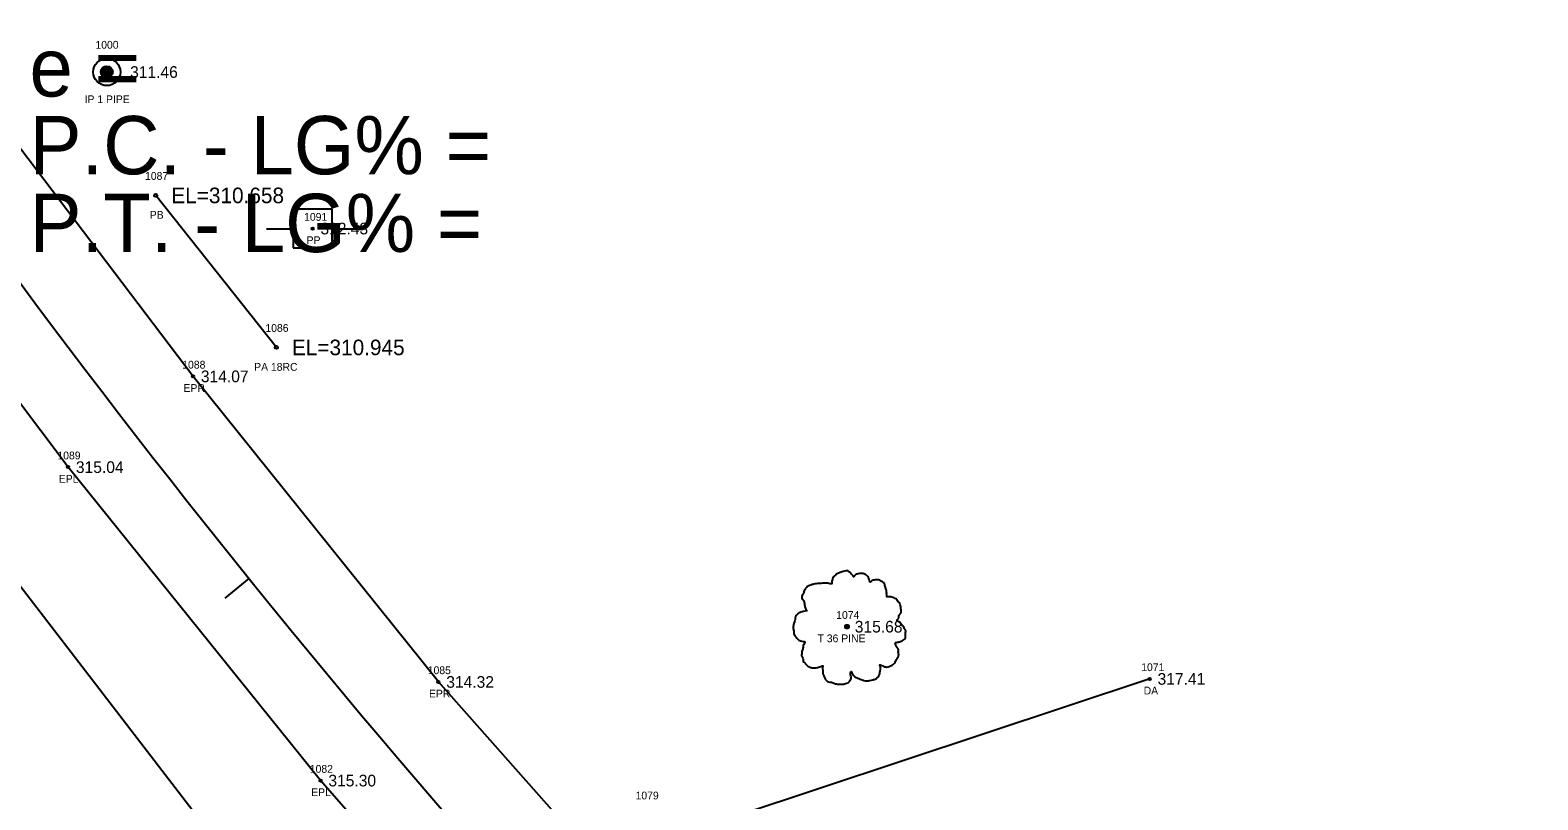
# Model space of a CAD drawing. Extents: x 1865045 to 1867370, y 910391 to 914218.
# Drawn here: x 1866620.1 to 1866814, y 910574.6 to 910673.5 of the extents above; entities that cross this region are included whole.
import ezdxf

# ---------------------------------------------------------------- set-up
doc = ezdxf.new("R2010")
doc.units = 0
for name, color, linetype in [('RD_EX_DR_Pipe', 7, 'Continuous'), ('RD_EX_DR_Pipe_txCode', 7, 'Continuous'), ('RD_EX_Driveway', 7, 'Continuous'), ('RD_EX_Driveway_txCode', 7, 'Continuous'), ('RD_EX_DV_Prop_txCode', 7, 'Continuous'), ('RD_EX_DV_PropPin', 7, 'Continuous'), ('RD_EX_Road', 7, 'Continuous'), ('RD_EX_Road_txCode', 7, 'Continuous'), ('RD_EX_TX_Driveway_ELEV', 7, 'Continuous'), ('RD_EX_TX_DV_Prop_ELEV', 7, 'Continuous'), ('RD_EX_TX_Road_ELEV', 7, 'Continuous'), ('RD_EX_TX_VEG_ELEV', 7, 'Continuous'), ('RD_EX_UT', 7, 'Continuous'), ('RD_EX_UT_txCode', 7, 'Continuous'), ('RD_EX_VEG', 7, 'Continuous'), ('RD_EX_VEG_txCode', 7, 'Continuous'), ('RD_HC_Cl', 7, 'Continuous'), ('RD_HC_Data', 7, 'Continuous'), ('RD_HC_Data_Tic', 7, 'Continuous'), ('RD_HC_Survey_ELEV', 7, 'Continuous'), ('RD_SMD_Locator', 7, 'Continuous'), ('RD_TX_Pipe_ElevEX', 7, 'Continuous')]:
    doc.layers.add(name, color=color, linetype=linetype)

msp = doc.modelspace()

# ---------------------------------------------------------------- linework, layer by layer
at = {"layer": 'RD_EX_DR_Pipe'}
msp.add_line((1866651.75, 910632.75), (1866636.24, 910652.29), dxfattribs=at)
at = {"layer": 'RD_EX_Driveway'}
msp.add_line((1866764.08, 910590.14), (1866711.01, 910572.54), dxfattribs=at)
at = {"layer": 'RD_EX_DV_PropPin'}
for p, q in [((1866629.21, 910667.96), (1866629.21, 910668.35)), ((1866629.24, 910667.85), (1866629.24, 910668.45)), ((1866629.28, 910667.78), (1866629.28, 910668.52)), ((1866629.31, 910667.73), (1866629.31, 910668.58)), ((1866629.35, 910667.68), (1866629.35, 910668.63)), ((1866629.38, 910667.64), (1866629.38, 910668.67)), ((1866629.42, 910667.6), (1866629.42, 910668.7)), ((1866629.45, 910667.57), (1866629.45, 910668.73)), ((1866629.49, 910667.54), (1866629.49, 910668.76)), ((1866629.52, 910667.52), (1866629.52, 910668.79)), ((1866629.56, 910667.5), (1866629.56, 910668.81)), ((1866629.59, 910667.48), (1866629.59, 910668.83)), ((1866629.63, 910667.46), (1866629.63, 910668.85)), ((1866629.66, 910667.45), (1866629.66, 910668.86)), ((1866629.7, 910667.43), (1866629.7, 910668.87)), ((1866629.73, 910667.42), (1866629.73, 910668.88)), ((1866629.77, 910667.41), (1866629.77, 910668.89)), ((1866629.8, 910667.4), (1866629.8, 910668.9)), ((1866629.84, 910667.4), (1866629.84, 910668.91)), ((1866629.87, 910667.4), (1866629.87, 910668.91)), ((1866629.91, 910667.39), (1866629.91, 910668.91)), ((1866629.94, 910667.39), (1866629.94, 910668.91)), ((1866629.98, 910667.39), (1866629.98, 910668.91)), ((1866630.01, 910667.4), (1866630.01, 910668.91)), ((1866630.05, 910667.4), (1866630.05, 910668.91)), ((1866630.08, 910667.4), (1866630.08, 910668.9)), ((1866630.12, 910667.41), (1866630.12, 910668.89)), ((1866630.15, 910667.42), (1866630.15, 910668.88)), ((1866630.19, 910667.43), (1866630.19, 910668.87)), ((1866630.22, 910667.45), (1866630.22, 910668.86)), ((1866630.26, 910667.46), (1866630.26, 910668.85)), ((1866630.29, 910667.48), (1866630.29, 910668.83)), ((1866630.33, 910667.5), (1866630.33, 910668.81)), ((1866630.36, 910667.52), (1866630.36, 910668.79)), ((1866630.4, 910667.54), (1866630.4, 910668.76)), ((1866630.43, 910667.57), (1866630.43, 910668.73)), ((1866630.47, 910667.6), (1866630.47, 910668.7)), ((1866630.51, 910667.64), (1866630.51, 910668.67)), ((1866630.54, 910667.68), (1866630.54, 910668.63)), ((1866630.58, 910667.73), (1866630.58, 910668.58)), ((1866630.61, 910667.78), (1866630.61, 910668.52)), ((1866630.65, 910667.85), (1866630.65, 910668.45)), ((1866630.68, 910667.96), (1866630.68, 910668.35))]:
    msp.add_line(p, q, dxfattribs=at)
for radius in [1.75, 0.761]:
    msp.add_circle((1866629.94, 910668.15), radius, dxfattribs=at)
at = {"layer": 'RD_EX_Road'}
for points in [[(1866813.99, 910446.88), (1866778.44, 910479.3), (1866742.34, 910514.45), (1866706.87, 910550.71), (1866695.16, 910564.33), (1866672.6, 910589.75), (1866641.04, 910629.03), (1866609.7, 910670.28), (1866582.23, 910711.25), (1866556.44, 910754.58), (1866532.04, 910798.87), (1866507.56, 910846.03), (1866483.5, 910895.43), (1866461.16, 910941.96), (1866414.86, 911037.95), (1866406.11, 911034.1)], [(1866800.58, 910432.45), (1866764.32, 910465.74), (1866727.39, 910500.95), (1866691.9, 910537.68), (1866657.44, 910577.07), (1866624.97, 910617.36), (1866593.69, 910658.89), (1866565.16, 910701.48), (1866538.98, 910745.57), (1866531.34, 910758.5), (1866513.94, 910791.05), (1866489.48, 910838.44), (1866465.73, 910886.02), (1866443.47, 910933.62), (1866397.5, 911029.82), (1866406.11, 911034.1)]]:
    msp.add_lwpolyline(points, dxfattribs=at)
at = {"layer": 'RD_EX_UT'}
for p, q in [((1866658.91, 910650.54), (1866653.91, 910650.54)), ((1866653.91, 910650.54), (1866653.91, 910645.54)), ((1866658.91, 910645.54), (1866658.91, 910650.54)), ((1866650.48, 910647.98), (1866653.95, 910647.98)), ((1866658.84, 910647.98), (1866662.48, 910647.98)), ((1866653.91, 910645.54), (1866658.91, 910645.54))]:
    msp.add_line(p, q, dxfattribs=at)
at = {"layer": 'RD_EX_VEG'}
msp.add_lwpolyline([(1866770.74, 910392.93), (1866734.38, 910438.07), (1866709.99, 910485.53), (1866679.02, 910526.15), (1866645.41, 910567.43), (1866612.91, 910609.64), (1866580.57, 910649.92), (1866452.86, 910898.44)], dxfattribs=at)
for centre, radius in [((1866725.14, 910596.85), 0.25), ((1866725.12, 910596.83), 0.0001)]:
    msp.add_circle(centre, radius, dxfattribs=at)
for points in [[(1866725.27, 910604.01), (1866724.97, 910604.04), (1866724.64, 910603.94), (1866724.39, 910603.84), (1866724.17, 910603.77), (1866723.94, 910603.67), (1866723.64, 910603.49), (1866723.42, 910603.29), (1866723.29, 910603.04), (1866723.24, 910602.82), (1866723.19, 910602.54), (1866723.19, 910602.37), (1866723.07, 910602.34), (1866722.92, 910602.37), (1866722.67, 910602.44), (1866722.42, 910602.44), (1866722.17, 910602.44), (1866721.82, 910602.42), (1866721.47, 910602.42), (1866721.19, 910602.37), (1866720.87, 910602.32), (1866720.49, 910602.19), (1866720.14, 910602.07), (1866719.85, 910601.82), (1866719.6, 910601.34), (1866719.47, 910600.99), (1866719.32, 910600.74), (1866719.47, 910600.29), (1866719.65, 910599.94), (1866719.67, 910599.74), (1866719.75, 910599.32), (1866719.85, 910599.09), (1866719.97, 910598.89), (1866719.9, 910598.87), (1866719.52, 910598.82), (1866719.22, 910598.72), (1866718.8, 910598.49), (1866718.57, 910598.27), (1866718.47, 910597.94), (1866718.45, 910597.59), (1866718.35, 910597.39), (1866718.27, 910597.12), (1866718.25, 910597.04), (1866718.2, 910596.72), (1866718.3, 910596.27), (1866718.32, 910595.92), (1866718.45, 910595.69), (1866718.6, 910595.52), (1866718.77, 910595.27), (1866719.17, 910595.04), (1866719.5, 910594.94), (1866719.7, 910594.92), (1866719.52, 910594.42), (1866719.47, 910594.07), (1866719.35, 910593.67), (1866719.35, 910593.59), (1866719.3, 910593.12), (1866719.45, 910592.79), (1866719.52, 910592.42), (1866719.7, 910592.2), (1866719.97, 910591.9), (1866720.29, 910591.67), (1866720.79, 910591.55), (1866721.19, 910591.57), (1866721.77, 910591.75), (1866722.02, 910591.82), (1866721.99, 910591.65), (1866722.02, 910591.27), (1866722.02, 910590.85), (1866722.17, 910590.52), (1866722.27, 910590.25), (1866722.42, 910590), (1866722.74, 910589.77), (1866723.14, 910589.7), (1866723.57, 910589.55), (1866724.02, 910589.47), (1866724.52, 910589.45), (1866725.12, 910589.6), (1866725.39, 910589.72), (1866725.49, 910589.9), (1866725.69, 910590.27), (1866725.64, 910590.5), (1866725.67, 910591.1), (1866725.77, 910590.92), (1866725.94, 910590.57), (1866726.44, 910590.27), (1866726.84, 910590.1), (1866727.32, 910589.95), (1866727.62, 910589.87), (1866728.09, 910589.95), (1866728.47, 910590.02), (1866728.84, 910590.15), (1866729.14, 910590.42), (1866729.32, 910590.7), (1866729.37, 910590.97), (1866729.44, 910591.35), (1866729.49, 910591.52)], [(1866729.49, 910591.52), (1866729.42, 910591.7), (1866729.37, 910591.95), (1866729.44, 910591.92), (1866729.62, 910591.87), (1866729.89, 910591.75), (1866730.12, 910591.67), (1866730.44, 910591.7), (1866730.72, 910591.8), (1866731.17, 910592.07), (1866731.44, 910592.54), (1866731.71, 910592.94), (1866731.79, 910593.27), (1866731.74, 910593.49), (1866731.71, 910593.99), (1866731.51, 910594.24), (1866731.46, 910594.37), (1866731.36, 910594.77), (1866731.44, 910594.82), (1866731.71, 910594.87), (1866732.09, 910594.99), (1866732.36, 910595.12), (1866732.59, 910595.29), (1866732.66, 910595.52), (1866732.64, 910595.92), (1866732.69, 910596.32), (1866732.61, 910596.47), (1866732.51, 910596.62), (1866732.44, 910596.82), (1866732.29, 910596.97), (1866732.19, 910597.12), (1866732.09, 910597.22), (1866731.96, 910597.37), (1866731.79, 910597.49), (1866731.64, 910597.54), (1866731.59, 910597.69), (1866731.74, 910597.89), (1866731.79, 910597.99), (1866731.81, 910598.22), (1866732.04, 910598.57), (1866732.09, 910598.97), (1866732.04, 910599.39), (1866731.99, 910599.67), (1866731.84, 910599.94), (1866731.64, 910600.19), (1866731.51, 910600.37), (1866731.34, 910600.49), (1866731.02, 910600.62), (1866730.77, 910600.67), (1866730.42, 910600.67), (1866730.22, 910600.72), (1866730.24, 910600.77), (1866730.24, 910600.92), (1866730.24, 910601.19), (1866730.17, 910601.64), (1866730.02, 910602.14), (1866730.02, 910602.17), (1866729.92, 910602.42), (1866729.69, 910602.62), (1866729.52, 910602.72), (1866729.32, 910602.84), (1866729.07, 910602.87), (1866728.77, 910602.87), (1866728.49, 910602.82), (1866728.29, 910602.72), (1866728.12, 910602.59), (1866728.04, 910602.74), (1866727.94, 910603.04), (1866727.89, 910603.19), (1866727.74, 910603.37), (1866727.52, 910603.57), (1866727.07, 910603.69), (1866726.44, 910603.62), (1866726.14, 910603.42), (1866725.99, 910603.24), (1866725.94, 910603.37), (1866725.74, 910603.57), (1866725.64, 910603.74), (1866725.47, 910603.87), (1866725.32, 910603.96), (1866725.22, 910604.01)]]:
    msp.add_spline(points, degree=3, dxfattribs=at)
at = {"layer": 'RD_HC_Cl'}
msp.add_arc((1867567.42, 911345.48), 1181.58, 205.67399, 227.8297, dxfattribs=at)
at = {"layer": 'RD_HC_Data_Tic'}
msp.add_line((1866648.23, 910603.04), (1866645.12, 910600.52), dxfattribs=at)
at = {"layer": 'RD_SMD_Locator'}
for centre, radius in [((1866629.94, 910668.15), 0.15), ((1866636.24, 910652.29), 0.2), ((1866656.42, 910648.03), 0.15), ((1866651.75, 910632.75), 0.2), ((1866641.04, 910629.03), 0.15), ((1866624.97, 910617.36), 0.15), ((1866725.14, 910596.85), 0.15), ((1866764.08, 910590.14), 0.15), ((1866672.6, 910589.75), 0.15), ((1866657.44, 910577.07), 0.15)]:
    msp.add_circle(centre, radius, dxfattribs=at)

# ---------------------------------------------------------------- texts
at = {"layer": 'RD_EX_DR_Pipe_txCode'}
for s, p in [('1087', (1866634.86, 910654.29)), ('PB', (1866635.47, 910649.29)), ('1086', (1866650.34, 910634.75)), ('PA 18RC', (1866648.9, 910629.75)), ('1079', (1866697.95, 910574.65))]:
    msp.add_text(s, height=1, dxfattribs=at).set_placement(p)
at = {"layer": 'RD_EX_Driveway_txCode'}
for s, p in [('1071', (1866762.98, 910591.14)), ('DA', (1866763.29, 910588.14))]:
    msp.add_text(s, height=1, dxfattribs=at).set_placement(p)
at = {"layer": 'RD_EX_DV_Prop_txCode'}
for s, p in [('1000', (1866628.48, 910671.15)), ('IP 1 PIPE', (1866627.09, 910664.15))]:
    msp.add_text(s, height=1, dxfattribs=at).set_placement(p)
at = {"layer": 'RD_EX_Road_txCode'}
for s, p in [('1088', (1866639.65, 910630.03)), ('EPR', (1866639.81, 910627.03)), ('1089', (1866623.59, 910618.36)), ('EPL', (1866623.77, 910615.36)), ('1085', (1866671.22, 910590.75)), ('EPR', (1866671.38, 910587.75)), ('1082', (1866656.05, 910578.07)), ('EPL', (1866656.23, 910575.07))]:
    msp.add_text(s, height=1, dxfattribs=at).set_placement(p)
at = {"layer": 'RD_EX_TX_Driveway_ELEV'}
msp.add_text('317.41', height=1.5, dxfattribs=at).set_placement((1866765.08, 910589.39))
at = {"layer": 'RD_EX_TX_DV_Prop_ELEV'}
msp.add_text('311.46', height=1.5, dxfattribs=at).set_placement((1866632.94, 910667.4))
at = {"layer": 'RD_EX_TX_Road_ELEV'}
for s, p in [('314.07', (1866642.04, 910628.28)), ('315.04', (1866625.97, 910616.61)), ('314.32', (1866673.6, 910589)), ('315.30', (1866658.44, 910576.32))]:
    msp.add_text(s, height=1.5, dxfattribs=at).set_placement(p)
at = {"layer": 'RD_EX_TX_VEG_ELEV'}
msp.add_text('315.68', height=1.5, dxfattribs=at).set_placement((1866726.14, 910596.1))
at = {"layer": 'RD_EX_UT_txCode'}
for s, p in [('1091', (1866655.32, 910649.03)), ('PP', (1866655.64, 910646.03))]:
    msp.add_text(s, height=1, dxfattribs=at).set_placement(p)
at = {"layer": 'RD_EX_VEG_txCode'}
for s, p in [('1074', (1866723.75, 910597.85)), ('T 36 PINE', (1866721.35, 910594.85))]:
    msp.add_text(s, height=1, dxfattribs=at).set_placement(p)
at = {"layer": 'RD_HC_Data'}
for s, p in [('e = ', (1866620, 910665)), ('P.C. - LG% = ', (1866620, 910655)), ('P.T. - LG% = ', (1866620, 910645))]:
    msp.add_text(s, height=7.5, dxfattribs=at).set_placement(p)
at = {"layer": 'RD_HC_Survey_ELEV'}
msp.add_text('312.43', height=1.5, dxfattribs=at).set_placement((1866657.42, 910647.28))
at = {"layer": 'RD_TX_Pipe_ElevEX'}
for s, p in [('EL=310.658', (1866638.24, 910651.29)), ('EL=310.945', (1866653.75, 910631.75))]:
    msp.add_text(s, height=2, dxfattribs=at).set_placement(p)

doc.saveas('drawing.dxf')
